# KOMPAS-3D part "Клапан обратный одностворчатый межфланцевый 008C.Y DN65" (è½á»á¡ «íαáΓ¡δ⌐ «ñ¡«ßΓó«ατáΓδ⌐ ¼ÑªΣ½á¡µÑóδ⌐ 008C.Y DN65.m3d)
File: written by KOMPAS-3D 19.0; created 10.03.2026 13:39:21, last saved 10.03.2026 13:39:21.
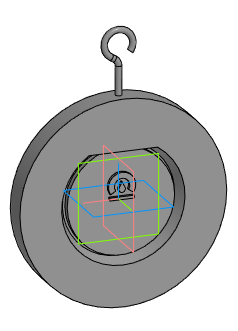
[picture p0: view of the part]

Document properties: Автор: Евгений; Полное имя файла: E:\Dendor\3D для проектировщиков\5.1 Тип 008C. Клапан обратный одностворчатый межфланцевый\stp_Клапан обратный одностворчатый межфланцевый 008C.Y\Клапан обратный одностворчатый межфланцевый 008C.Y DN65.m3d

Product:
- Part/product: Клапан обратный одностворчатый межфланцевый 008C.Y DN65

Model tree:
1. Операция без истории:1  (labels: Клапан обратный одностворчатый межфланцевый 008C.Y DN65)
